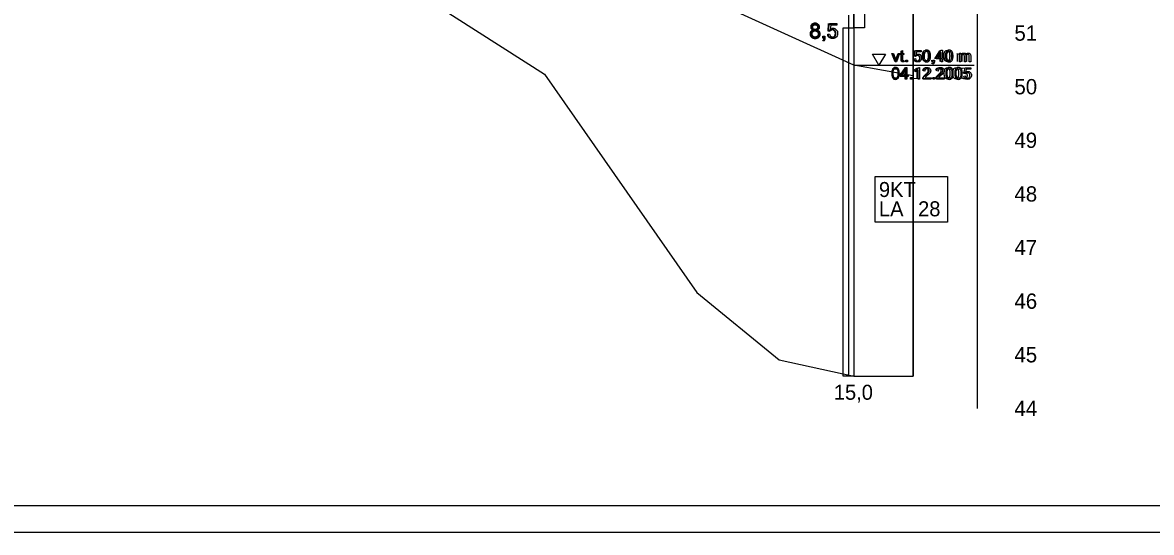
# Model space of a CAD drawing. Extents: x 532503 to 539665, y 6557663 to 6561526.
# Drawn here: x 537565.3 to 537986.3, y 6559459.7 to 6559649.9 of the extents above; entities that cross this region are included whole.
import ezdxf

# ---------------------------------------------------------------- set-up
doc = ezdxf.new("R2010")
doc.units = 0
for name, color, linetype in [('ABIJOONIS', 7, 'Continuous'), ('GEOLPUNKT', 7, 'Continuous'), ('mõõtpost parem', 7, 'Continuous'), ('Plokid', 7, 'Continuous'), ('Proovid', 7, 'Continuous'), ('Täide', 7, 'Continuous'), ('Veetase', 7, 'Continuous'), ('VORMISTUS', 7, 'Continuous')]:
    doc.layers.add(name, color=color, linetype=linetype)

msp = doc.modelspace()

# ---------------------------------------------------------------- linework, layer by layer
at = {"layer": 'ABIJOONIS'}
msp.add_lwpolyline([(536964.69, 6560679.71), (539664.69, 6560679.71), (539664.69, 6559459.71), (536964.69, 6559459.71), (536964.69, 6560679.71)], dxfattribs=at)
at = {"layer": 'GEOLPUNKT'}
msp.add_line((537875.25, 6559818), (537875.25, 6559518), dxfattribs=at)
at = {"layer": 'mõõtpost parem'}
msp.add_line((537921.46, 6559506), (537921.46, 6559986), dxfattribs=at)
at = {"layer": 'Plokid'}
msp.add_line((537873.25, 6559652.73), (537873.25, 6559518.45), dxfattribs=at)
at = {"layer": 'Proovid'}
for points in [[(537875.25, 6559778), (537879.25, 6559778), (537879.25, 6559648), (537875.25, 6559648)], [(537871.25, 6559648), (537875.25, 6559648), (537875.25, 6559518), (537871.25, 6559518)], [(537883.25, 6559592.44), (537910.25, 6559592.44), (537910.25, 6559575.44), (537883.25, 6559575.44)]]:
    msp.add_lwpolyline(points, close=True, dxfattribs=at)
for points in [[(537866.3, 6559646.63), (537865.66, 6559646.71), (537866.2, 6559649.59), (537868.98, 6559649.59), (537868.98, 6559648.93), (537866.75, 6559648.93), (537866.45, 6559647.43)], [(537863.73, 6559644.06), (537863.73, 6559644.84), (537864.51, 6559644.84), (537864.51, 6559644.06)], [(537865.53, 6559645.53), (537866.25, 6559645.59)], [(537863.88, 6559642.95), (537863.69, 6559643.24)], [(537864.12, 6559644.06), (537863.73, 6559644.06)]]:
    msp.add_lwpolyline(points, dxfattribs=at)
for points in [[(537860.07, 6559647.1), (537859.64, 6559647.26), (537859.44, 6559647.55), (537859.23, 6559647.84), (537859.23, 6559648.24), (537859.23, 6559648.85), (537859.67, 6559649.27), (537860.11, 6559649.68), (537860.84, 6559649.68), (537861.57, 6559649.68), (537862.01, 6559649.26), (537862.46, 6559648.83), (537862.46, 6559648.22), (537862.46, 6559647.83), (537862.26, 6559647.54), (537862.05, 6559647.26), (537861.63, 6559647.1), (537862.15, 6559646.93), (537862.42, 6559646.56), (537862.69, 6559646.18), (537862.69, 6559645.66), (537862.69, 6559644.94), (537862.18, 6559644.45), (537861.68, 6559643.97), (537860.85, 6559643.97), (537860.02, 6559643.97), (537859.51, 6559644.46), (537859, 6559644.95), (537859, 6559645.68), (537859, 6559646.23), (537859.28, 6559646.6), (537859.56, 6559646.97), (537860.07, 6559647.1)], [(537859.94, 6559648.26), (537859.94, 6559647.87), (537860.19, 6559647.62), (537860.44, 6559647.36), (537860.85, 6559647.36), (537861.25, 6559647.36), (537861.5, 6559647.61), (537861.75, 6559647.86), (537861.75, 6559648.23), (537861.75, 6559648.6), (537861.49, 6559648.86), (537861.23, 6559649.12), (537860.84, 6559649.12), (537860.45, 6559649.12), (537860.19, 6559648.87), (537859.94, 6559648.61), (537859.94, 6559648.26)], [(537859.71, 6559645.68), (537859.71, 6559645.38), (537859.85, 6559645.11), (537859.99, 6559644.83), (537860.26, 6559644.68), (537860.54, 6559644.53), (537860.85, 6559644.53), (537861.35, 6559644.53), (537861.66, 6559644.85), (537861.98, 6559645.16), (537861.98, 6559645.65), (537861.98, 6559646.15), (537861.65, 6559646.48), (537861.33, 6559646.8), (537860.83, 6559646.8), (537860.34, 6559646.8), (537860.03, 6559646.48), (537859.71, 6559646.16), (537859.71, 6559645.68)], [(537866.45, 6559647.43), (537866.95, 6559647.78), (537867.51, 6559647.78), (537868.24, 6559647.78), (537868.74, 6559647.27), (537869.25, 6559646.76), (537869.25, 6559645.96), (537869.25, 6559645.2), (537868.8, 6559644.65), (537868.27, 6559643.97), (537867.33, 6559643.97), (537866.57, 6559643.97), (537866.09, 6559644.39), (537865.6, 6559644.82), (537865.53, 6559645.53)], [(537866.25, 6559645.59), (537866.34, 6559645.06), (537866.63, 6559644.79), (537866.92, 6559644.53), (537867.33, 6559644.53), (537867.83, 6559644.53), (537868.17, 6559644.9), (537868.52, 6559645.28), (537868.52, 6559645.9), (537868.52, 6559646.49), (537868.19, 6559646.83), (537867.86, 6559647.17), (537867.32, 6559647.17), (537866.99, 6559647.17), (537866.72, 6559647.02), (537866.45, 6559646.87), (537866.3, 6559646.63)], [(537863.69, 6559643.24), (537863.9, 6559643.34), (537864.01, 6559643.53), (537864.11, 6559643.71), (537864.12, 6559644.06)], [(537864.51, 6559644.06), (537864.51, 6559643.63), (537864.36, 6559643.36), (537864.21, 6559643.1), (537863.88, 6559642.95)]]:
    msp.add_open_spline(points, degree=3, dxfattribs=at)
at = {"layer": 'Täide'}
for points in [[(537897.46, 6559814.89), (537897.46, 6559636), (537897.46, 6559518)], [(537897.46, 6559518), (537897.46, 6559636), (537897.46, 6559757.41)], [(537897.46, 6559518), (537897.46, 6559636), (537897.46, 6559757.41)], [(537303.91, 6559646.73), (537332.99, 6559646), (537596.15, 6559687.6), (537701.31, 6559668.24), (537759.9, 6559630.65), (537816.72, 6559549.2), (537847.4, 6559524.13), (537875.25, 6559518), (537897.46, 6559518)], [(537303.91, 6559646.73), (537332.99, 6559646), (537596.15, 6559687.6), (537701.31, 6559668.24), (537759.9, 6559630.65), (537816.72, 6559549.2), (537847.4, 6559524.13), (537875.25, 6559518), (537897.46, 6559518)], [(537303.91, 6559646.73), (537332.99, 6559646), (537596.15, 6559687.6), (537701.31, 6559668.24), (537759.9, 6559630.65), (537816.72, 6559549.2), (537847.4, 6559524.13), (537875.25, 6559518), (537897.46, 6559518)]]:
    msp.add_lwpolyline(points, dxfattribs=at)
at = {"layer": 'Veetase'}
msp.add_lwpolyline([(537897.46, 6559630.11), (537875.25, 6559634), (537737.03, 6559696.96), (537596.15, 6559741.6), (537333, 6559712), (537303.91, 6559709.89)], dxfattribs=at)
at = {"layer": 'VORMISTUS'}
msp.add_line((537875.25, 6559634), (537920.12, 6559634), dxfattribs=at)
for points in [[(537004.69, 6559469.71), (539654.69, 6559469.71), (539654.69, 6560669.71), (537004.69, 6560669.71)], [(537884.66, 6559638.14), (537887.05, 6559638.14), (537884.66, 6559634), (537882.27, 6559638.14)]]:
    msp.add_lwpolyline(points, close=True, dxfattribs=at)
for points in [[(537890.68, 6559635.3), (537889.49, 6559638.43), (537890.05, 6559638.43), (537890.72, 6559636.55)], [(537891.12, 6559636.52), (537891.82, 6559638.43), (537892.36, 6559638.43), (537891.18, 6559635.3), (537890.68, 6559635.3)], [(537892.93, 6559636.21), (537892.93, 6559638.02), (537892.54, 6559638.02), (537892.54, 6559638.43), (537892.93, 6559638.43), (537892.93, 6559639.2), (537893.46, 6559639.52), (537893.46, 6559638.43), (537893.99, 6559638.43), (537893.99, 6559638.02), (537893.46, 6559638.02), (537893.46, 6559636.18)], [(537897.71, 6559636.43), (537898.27, 6559636.47)], [(537898.31, 6559637.27), (537897.81, 6559637.34), (537898.23, 6559639.56), (537900.38, 6559639.56), (537900.38, 6559639.05), (537898.65, 6559639.05), (537898.42, 6559637.89)], [(537907.8, 6559635.3), (537907.8, 6559636.33), (537905.93, 6559636.33), (537905.93, 6559636.82), (537907.9, 6559639.62), (537908.33, 6559639.62), (537908.33, 6559636.82), (537908.91, 6559636.82), (537908.91, 6559636.33), (537908.33, 6559636.33), (537908.33, 6559635.3), (537907.8, 6559635.3)], [(537907.8, 6559636.82), (537907.8, 6559638.77), (537906.45, 6559636.82), (537907.8, 6559636.82)], [(537914.64, 6559635.3), (537914.64, 6559638.43), (537915.11, 6559638.43), (537915.11, 6559637.99)], [(537915.17, 6559636.92), (537915.17, 6559635.3), (537914.64, 6559635.3)], [(537917.03, 6559637.11), (537917.03, 6559635.3), (537916.5, 6559635.3), (537916.5, 6559637.33)], [(537918.88, 6559637.44), (537918.88, 6559635.3), (537918.35, 6559635.3), (537918.35, 6559637.27)], [(537894.48, 6559628.82), (537894.48, 6559629.85), (537892.6, 6559629.85), (537892.6, 6559630.34), (537894.57, 6559633.14), (537895.01, 6559633.14), (537895.01, 6559630.34), (537895.59, 6559630.34), (537895.59, 6559629.85), (537895.01, 6559629.85), (537895.01, 6559628.82), (537894.48, 6559628.82)], [(537894.48, 6559630.34), (537894.48, 6559632.29), (537893.12, 6559630.34), (537894.48, 6559630.34)], [(537893.99, 6559635.77), (537894.07, 6559635.3)], [(537894.66, 6559635.3), (537894.66, 6559635.9), (537895.26, 6559635.9), (537895.26, 6559635.3), (537894.66, 6559635.3)], [(537898.21, 6559631.56), (537898.21, 6559632.07)], [(537899.8, 6559628.82), (537899.27, 6559628.82), (537899.27, 6559632.2)], [(537899.46, 6559633.15), (537899.8, 6559633.15), (537899.8, 6559628.82)], [(537904.82, 6559634.44), (537904.68, 6559634.67)], [(537904.71, 6559635.3), (537904.71, 6559635.9), (537905.31, 6559635.9), (537905.31, 6559635.3)], [(537905.01, 6559635.3), (537904.71, 6559635.3)], [(537916.85, 6559630.79), (537916.36, 6559630.86), (537916.77, 6559633.08), (537918.92, 6559633.08), (537918.92, 6559632.57), (537917.2, 6559632.57), (537916.97, 6559631.41)], [(537896.43, 6559628.82), (537896.43, 6559629.42), (537897.03, 6559629.42), (537897.03, 6559628.82), (537896.43, 6559628.82)], [(537903.95, 6559629.33), (537903.95, 6559628.82), (537901.09, 6559628.82)], [(537901.74, 6559631.85), (537901.19, 6559631.9)], [(537901.83, 6559629.33), (537903.95, 6559629.33)], [(537904.82, 6559628.82), (537904.82, 6559629.42), (537905.42, 6559629.42), (537905.42, 6559628.82), (537904.82, 6559628.82)], [(537908.98, 6559629.33), (537908.98, 6559628.82), (537906.13, 6559628.82)], [(537906.77, 6559631.85), (537906.22, 6559631.9)], [(537906.86, 6559629.33), (537908.98, 6559629.33)], [(537916.26, 6559629.95), (537916.82, 6559629.99)]]:
    msp.add_lwpolyline(points, dxfattribs=at)
for points in [[(537890.72, 6559636.55), (537890.83, 6559636.25), (537890.92, 6559635.92), (537890.99, 6559636.17), (537891.12, 6559636.52)], [(537894.07, 6559635.3), (537893.84, 6559635.25), (537893.67, 6559635.25), (537893.38, 6559635.25), (537893.22, 6559635.34), (537893.06, 6559635.44), (537893, 6559635.59), (537892.93, 6559635.73), (537892.93, 6559636.21)], [(537893.46, 6559636.18), (537893.46, 6559635.95), (537893.49, 6559635.89), (537893.52, 6559635.82), (537893.58, 6559635.79), (537893.64, 6559635.75), (537893.76, 6559635.75), (537893.85, 6559635.75), (537893.99, 6559635.77)], [(537898.42, 6559637.89), (537898.81, 6559638.16), (537899.24, 6559638.16), (537899.8, 6559638.16), (537900.19, 6559637.77), (537900.58, 6559637.38), (537900.58, 6559636.76), (537900.58, 6559636.18), (537900.24, 6559635.75), (537899.82, 6559635.22), (537899.1, 6559635.22), (537898.51, 6559635.22), (537898.14, 6559635.55), (537897.77, 6559635.88), (537897.71, 6559636.43)], [(537898.27, 6559636.47), (537898.33, 6559636.07), (537898.56, 6559635.86), (537898.78, 6559635.66), (537899.1, 6559635.66), (537899.49, 6559635.66), (537899.75, 6559635.95), (537900.02, 6559636.24), (537900.02, 6559636.72), (537900.02, 6559637.17), (537899.76, 6559637.43), (537899.51, 6559637.7), (537899.09, 6559637.7), (537898.84, 6559637.7), (537898.63, 6559637.58), (537898.43, 6559637.46), (537898.31, 6559637.27)], [(537901.07, 6559637.43), (537901.07, 6559638.19), (537901.23, 6559638.66), (537901.39, 6559639.13), (537901.7, 6559639.38), (537902.01, 6559639.63), (537902.48, 6559639.63), (537902.83, 6559639.63), (537903.09, 6559639.49), (537903.35, 6559639.35), (537903.52, 6559639.09), (537903.69, 6559638.83), (537903.79, 6559638.45), (537903.89, 6559638.07), (537903.89, 6559637.43), (537903.89, 6559636.67), (537903.73, 6559636.2), (537903.57, 6559635.73), (537903.26, 6559635.48), (537902.95, 6559635.22), (537902.48, 6559635.22), (537901.85, 6559635.22), (537901.5, 6559635.67), (537901.07, 6559636.21), (537901.07, 6559637.43)], [(537901.62, 6559637.43), (537901.62, 6559636.36), (537901.86, 6559636.01), (537902.11, 6559635.66), (537902.48, 6559635.66), (537902.84, 6559635.66), (537903.09, 6559636.01), (537903.34, 6559636.36), (537903.34, 6559637.43), (537903.34, 6559638.49), (537903.09, 6559638.84), (537902.84, 6559639.19), (537902.47, 6559639.19), (537902.11, 6559639.19), (537901.89, 6559638.89), (537901.62, 6559638.49), (537901.62, 6559637.43)], [(537909.46, 6559637.43), (537909.46, 6559638.19), (537909.61, 6559638.66), (537909.77, 6559639.13), (537910.08, 6559639.38), (537910.39, 6559639.63), (537910.86, 6559639.63), (537911.21, 6559639.63), (537911.47, 6559639.49), (537911.74, 6559639.35), (537911.91, 6559639.09), (537912.08, 6559638.83), (537912.17, 6559638.45), (537912.27, 6559638.07), (537912.27, 6559637.43), (537912.27, 6559636.67), (537912.12, 6559636.2), (537911.96, 6559635.73), (537911.65, 6559635.48), (537911.34, 6559635.22), (537910.86, 6559635.22), (537910.24, 6559635.22), (537909.88, 6559635.67), (537909.46, 6559636.21), (537909.46, 6559637.43)], [(537910, 6559637.43), (537910, 6559636.36), (537910.25, 6559636.01), (537910.5, 6559635.66), (537910.86, 6559635.66), (537911.23, 6559635.66), (537911.48, 6559636.01), (537911.73, 6559636.36), (537911.73, 6559637.43), (537911.73, 6559638.49), (537911.48, 6559638.84), (537911.23, 6559639.19), (537910.86, 6559639.19), (537910.49, 6559639.19), (537910.28, 6559638.89), (537910, 6559638.49), (537910, 6559637.43)], [(537915.11, 6559637.99), (537915.26, 6559638.22), (537915.5, 6559638.36), (537915.75, 6559638.5), (537916.06, 6559638.5), (537916.41, 6559638.5), (537916.63, 6559638.35), (537916.85, 6559638.21), (537916.94, 6559637.95), (537917.32, 6559638.5), (537917.91, 6559638.5), (537918.38, 6559638.5), (537918.63, 6559638.24), (537918.88, 6559637.98), (537918.88, 6559637.44)], [(537916.5, 6559637.33), (537916.5, 6559637.68), (537916.37, 6559637.86), (537916.24, 6559638.04), (537915.94, 6559638.04), (537915.72, 6559638.04), (537915.53, 6559637.92), (537915.34, 6559637.8), (537915.25, 6559637.57), (537915.17, 6559637.35), (537915.17, 6559636.92)], [(537918.35, 6559637.27), (537918.35, 6559637.58), (537918.3, 6559637.72), (537918.25, 6559637.86), (537918.11, 6559637.95), (537917.97, 6559638.04), (537917.79, 6559638.04), (537917.46, 6559638.04), (537917.24, 6559637.82), (537917.03, 6559637.6), (537917.03, 6559637.11)], [(537889.42, 6559630.95), (537889.42, 6559631.71), (537889.58, 6559632.18), (537889.74, 6559632.65), (537890.05, 6559632.9), (537890.36, 6559633.15), (537890.83, 6559633.15), (537891.18, 6559633.15), (537891.44, 6559633.01), (537891.7, 6559632.87), (537891.87, 6559632.61), (537892.04, 6559632.35), (537892.14, 6559631.97), (537892.24, 6559631.59), (537892.24, 6559630.95), (537892.24, 6559630.19), (537892.08, 6559629.72), (537891.93, 6559629.25), (537891.61, 6559629), (537891.3, 6559628.74), (537890.83, 6559628.74), (537890.21, 6559628.74), (537889.85, 6559629.19), (537889.42, 6559629.73), (537889.42, 6559630.95)], [(537889.97, 6559630.95), (537889.97, 6559629.88), (537890.22, 6559629.53), (537890.47, 6559629.18), (537890.83, 6559629.18), (537891.19, 6559629.18), (537891.44, 6559629.53), (537891.69, 6559629.88), (537891.69, 6559630.95), (537891.69, 6559632.01), (537891.44, 6559632.36), (537891.19, 6559632.71), (537890.82, 6559632.71), (537890.46, 6559632.71), (537890.24, 6559632.41), (537889.97, 6559632.01), (537889.97, 6559630.95)], [(537898.21, 6559632.07), (537898.66, 6559632.28), (537898.99, 6559632.58), (537899.32, 6559632.87), (537899.46, 6559633.15)], [(537899.27, 6559632.2), (537899.08, 6559632.01), (537898.77, 6559631.83), (537898.46, 6559631.65), (537898.21, 6559631.56)], [(537901.09, 6559628.82), (537901.09, 6559629.01), (537901.16, 6559629.18), (537901.27, 6559629.48), (537901.51, 6559629.76), (537901.75, 6559630.04), (537902.2, 6559630.41), (537902.9, 6559630.99), (537903.15, 6559631.33), (537903.4, 6559631.67), (537903.4, 6559631.97), (537903.4, 6559632.28), (537903.17, 6559632.5), (537902.95, 6559632.71), (537902.58, 6559632.71), (537902.2, 6559632.71), (537901.97, 6559632.48), (537901.74, 6559632.26), (537901.74, 6559631.85)], [(537901.19, 6559631.9), (537901.25, 6559632.51), (537901.61, 6559632.83), (537901.98, 6559633.15), (537902.6, 6559633.15), (537903.22, 6559633.15), (537903.58, 6559632.81), (537903.94, 6559632.46), (537903.94, 6559631.95), (537903.94, 6559631.69), (537903.84, 6559631.44), (537903.73, 6559631.19), (537903.49, 6559630.92), (537903.24, 6559630.64), (537902.67, 6559630.16), (537902.19, 6559629.76), (537902.06, 6559629.61), (537901.92, 6559629.47), (537901.83, 6559629.33)], [(537904.68, 6559634.67), (537904.84, 6559634.74), (537904.92, 6559634.88), (537905, 6559635.03), (537905.01, 6559635.3)], [(537905.31, 6559635.3), (537905.31, 6559634.96), (537905.2, 6559634.76), (537905.08, 6559634.55), (537904.82, 6559634.44)], [(537906.13, 6559628.82), (537906.12, 6559629.01), (537906.19, 6559629.18), (537906.3, 6559629.48), (537906.54, 6559629.76), (537906.78, 6559630.04), (537907.23, 6559630.41), (537907.93, 6559630.99), (537908.18, 6559631.33), (537908.43, 6559631.67), (537908.43, 6559631.97), (537908.43, 6559632.28), (537908.2, 6559632.5), (537907.98, 6559632.71), (537907.62, 6559632.71), (537907.23, 6559632.71), (537907, 6559632.48), (537906.77, 6559632.26), (537906.77, 6559631.85)], [(537906.22, 6559631.9), (537906.28, 6559632.51), (537906.65, 6559632.83), (537907.01, 6559633.15), (537907.63, 6559633.15), (537908.25, 6559633.15), (537908.61, 6559632.81), (537908.97, 6559632.46), (537908.97, 6559631.95), (537908.97, 6559631.69), (537908.87, 6559631.44), (537908.76, 6559631.19), (537908.52, 6559630.92), (537908.27, 6559630.64), (537907.7, 6559630.16), (537907.22, 6559629.76), (537907.09, 6559629.61), (537906.95, 6559629.47), (537906.86, 6559629.33)], [(537909.55, 6559630.95), (537909.55, 6559631.71), (537909.71, 6559632.18), (537909.87, 6559632.65), (537910.18, 6559632.9), (537910.49, 6559633.15), (537910.96, 6559633.15), (537911.31, 6559633.15), (537911.57, 6559633.01), (537911.83, 6559632.87), (537912, 6559632.61), (537912.17, 6559632.35), (537912.27, 6559631.97), (537912.37, 6559631.59), (537912.37, 6559630.95), (537912.37, 6559630.19), (537912.21, 6559629.72), (537912.05, 6559629.25), (537911.74, 6559629), (537911.43, 6559628.74), (537910.96, 6559628.74), (537910.33, 6559628.74), (537909.98, 6559629.19), (537909.55, 6559629.73), (537909.55, 6559630.95)], [(537910.1, 6559630.95), (537910.1, 6559629.88), (537910.35, 6559629.53), (537910.59, 6559629.18), (537910.96, 6559629.18), (537911.32, 6559629.18), (537911.57, 6559629.53), (537911.82, 6559629.88), (537911.82, 6559630.95), (537911.82, 6559632.01), (537911.57, 6559632.36), (537911.32, 6559632.71), (537910.95, 6559632.71), (537910.59, 6559632.71), (537910.37, 6559632.41), (537910.1, 6559632.01), (537910.1, 6559630.95)], [(537912.91, 6559630.95), (537912.91, 6559631.71), (537913.06, 6559632.18), (537913.22, 6559632.65), (537913.53, 6559632.9), (537913.84, 6559633.15), (537914.31, 6559633.15), (537914.66, 6559633.15), (537914.92, 6559633.01), (537915.19, 6559632.87), (537915.36, 6559632.61), (537915.53, 6559632.35), (537915.62, 6559631.97), (537915.72, 6559631.59), (537915.72, 6559630.95), (537915.72, 6559630.19), (537915.56, 6559629.72), (537915.41, 6559629.25), (537915.1, 6559629), (537914.79, 6559628.74), (537914.31, 6559628.74), (537913.69, 6559628.74), (537913.33, 6559629.19), (537912.91, 6559629.73), (537912.91, 6559630.95)], [(537913.45, 6559630.95), (537913.45, 6559629.88), (537913.7, 6559629.53), (537913.95, 6559629.18), (537914.31, 6559629.18), (537914.68, 6559629.18), (537914.93, 6559629.53), (537915.17, 6559629.88), (537915.17, 6559630.95), (537915.17, 6559632.01), (537914.93, 6559632.36), (537914.68, 6559632.71), (537914.31, 6559632.71), (537913.94, 6559632.71), (537913.72, 6559632.41), (537913.45, 6559632.01), (537913.45, 6559630.95)], [(537916.97, 6559631.41), (537917.35, 6559631.68), (537917.78, 6559631.68), (537918.35, 6559631.68), (537918.74, 6559631.29), (537919.13, 6559630.9), (537919.13, 6559630.28), (537919.13, 6559629.7), (537918.78, 6559629.27), (537918.37, 6559628.74), (537917.65, 6559628.74), (537917.06, 6559628.74), (537916.69, 6559629.07), (537916.31, 6559629.4), (537916.26, 6559629.95)], [(537916.82, 6559629.99), (537916.88, 6559629.59), (537917.1, 6559629.38), (537917.33, 6559629.18), (537917.65, 6559629.18), (537918.03, 6559629.18), (537918.3, 6559629.47), (537918.56, 6559629.76), (537918.56, 6559630.24), (537918.56, 6559630.69), (537918.31, 6559630.95), (537918.06, 6559631.22), (537917.64, 6559631.22), (537917.38, 6559631.22), (537917.18, 6559631.1), (537916.97, 6559630.98), (537916.85, 6559630.79)]]:
    msp.add_open_spline(points, degree=3, dxfattribs=at)

# ---------------------------------------------------------------- texts
at = {"layer": 'GEOLPUNKT'}
msp.add_text('15,0', height=5.6, dxfattribs=at).set_placement((537867.82, 6559509.2))
at = {"layer": 'mõõtpost parem'}
for s, p in [('51', (537935.16, 6559643.15)), ('50', (537935.16, 6559623.15)), ('49', (537935.16, 6559603.15)), ('48', (537935.16, 6559583.15)), ('47', (537935.16, 6559563.15)), ('46', (537935.16, 6559543.15)), ('45', (537935.16, 6559523.15)), ('44', (537935.16, 6559503.15))]:
    msp.add_text(s, height=5.7, dxfattribs=at).set_placement(p)
at = {"layer": 'Proovid'}
for s, p in [('8,5', (537858.69, 6559644.06)), ('9KT', (537884.65, 6559584.84)), ('LA', (537884.65, 6559577.64)), ('28', (537899.25, 6559577.64))]:
    msp.add_text(s, height=5.6, dxfattribs=at).set_placement(p)
at = {"layer": 'VORMISTUS'}
for s, p in [('vt. 50,40 m', (537889.42, 6559635.3)), ('04.12.2005', (537889.17, 6559628.82))]:
    msp.add_text(s, height=4.32, dxfattribs=at).set_placement(p)

doc.saveas('drawing.dxf')
